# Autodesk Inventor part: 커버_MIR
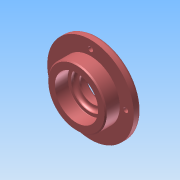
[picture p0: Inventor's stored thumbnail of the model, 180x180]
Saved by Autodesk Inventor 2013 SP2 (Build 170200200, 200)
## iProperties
Created: 2026-07
Part Number: 커버_MIR
Material: Generic
Document SubType Name: Modeling
Designer: aa
Density: 1 g/cm^3
Author: aa
변환 표준: STEP AP214IS
전처리기: Build: 200, Release: 2013 SP2 Update 6 - Date: Thu 07/17/2014
전송 단위: 밀리미터
불확실성: 0.01
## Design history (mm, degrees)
derived "커버.ipt"
feature "솔리드1::커버.ipt" dims "d0" = 10
tag "피쳐 태그1"
node "솔리드1"
